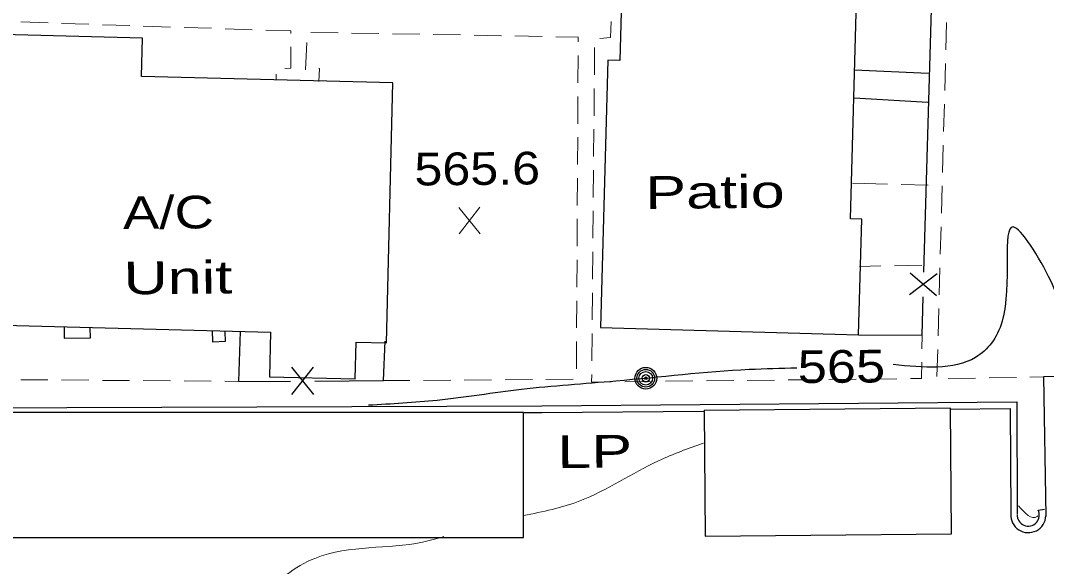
# Model space of a CAD drawing. Extents: x 2361708 to 2370558, y 6977955 to 6991887.
# Drawn here: x 2366045.4 to 2366196.1, y 6987005.8 to 6987086 of the extents above; entities that cross this region are included whole.
import ezdxf
from ezdxf.enums import TextEntityAlignment as Align

# ---------------------------------------------------------------- set-up
doc = ezdxf.new("R2010")
doc.units = 0
doc.header["$LTSCALE"] = 1.9
for name, color, linetype, lineweight in [('11', 7, 'Continuous', 25), ('13', 7, 'Continuous', 13), ('14', 7, 'Continuous', 13), ('17', 7, 'Continuous', 25), ('2', 7, 'Continuous', 25), ('20', 7, 'Continuous', 25), ('23', 7, 'Continuous', 25), ('31', 7, 'Continuous', 13), ('35', 7, 'Continuous', 13)]:
    doc.layers.add(name, color=color, linetype=linetype, lineweight=lineweight)

msp = doc.modelspace()

# ---------------------------------------------------------------- linework, layer by layer
at = {"layer": '11'}
for points in [[(2366135.939, 6987170.918), (2366133.413, 6987080.11), (2366131.692, 6987080.163), (2366130.576, 6987040.891), (2366168.498, 6987039.812), (2366168.976, 6987056.797), (2366167.316, 6987056.842), (2366171.07, 6987192.024), (2366172.87, 6987191.971), (2366173.763, 6987225.311), (2366137.182, 6987226.293), (2366136.753, 6987210.428), (2366134.822, 6987210.48), (2366133.798, 6987170.978)], [(2365971.868, 6987043.1), (2366082.12, 6987040.2), (2366081.953, 6987033.648), (2366094.536, 6987033.318), (2366094.675, 6987038.719), (2366099.136, 6987038.612), (2366100.092, 6987076.843), (2366063.132, 6987077.771), (2366063.278, 6987083.403), (2366042.702, 6987083.917), (2366042.601, 6987079.885), (2365992.386, 6987081.197), (2365992.488, 6987085.159), (2365972.982, 6987085.673)], [(2366145.969, 6987010.236), (2366182.187, 6987010.56), (2366182.021, 6987029.01), (2366145.803, 6987028.685)], [(2366029.615, 6987010.008), (2366119.26, 6987010.002), (2366119.255, 6987028.393), (2366029.61, 6987028.389)]]:
    msp.add_lwpolyline(points, close=True, dxfattribs=at)
at = {"layer": '13'}
for p, q in [((2366045.405, 6987085.762), (2366049.406, 6987085.631)), ((2366051.407, 6987085.56), (2366055.409, 6987085.428)), ((2366057.409, 6987085.357), (2366061.411, 6987085.225)), ((2366063.412, 6987085.154), (2366067.413, 6987085.022)), ((2366069.414, 6987084.961), (2366073.415, 6987084.829)), ((2366075.416, 6987084.758), (2366079.418, 6987084.626)), ((2366088.021, 6987084.228), (2366092.023, 6987084.156)), ((2366181.34, 6987081.676), (2366181.452, 6987085.677)), ((2366087.254, 6987078.751), (2366087.445, 6987082.742)), ((2366094.023, 6987084.125), (2366098.024, 6987084.053)), ((2366100.024, 6987084.023), (2366104.025, 6987083.95)), ((2366106.025, 6987083.92), (2366110.026, 6987083.848)), ((2366112.027, 6987083.807), (2366116.028, 6987083.735)), ((2366118.028, 6987083.704), (2366122.029, 6987083.632)), ((2366129.693, 6987077.994), (2366129.725, 6987081.995)), ((2366127.306, 6987080.822), (2366127.284, 6987076.821)), ((2366181.177, 6987075.674), (2366181.289, 6987079.675)), ((2366082.94, 6987078.089), (2366082.946, 6987077.379)), ((2366129.64, 6987071.993), (2366129.672, 6987075.994)), ((2366127.273, 6987074.821), (2366127.251, 6987070.821)), ((2366181.015, 6987069.673), (2366181.126, 6987073.674)), ((2366129.587, 6987065.993), (2366129.619, 6987069.993)), ((2366127.24, 6987068.821), (2366127.218, 6987064.82)), ((2366180.852, 6987063.671), (2366180.964, 6987067.672)), ((2366129.534, 6987059.992), (2366129.566, 6987063.992)), ((2366127.208, 6987062.82), (2366127.186, 6987058.82)), ((2366180.689, 6987057.669), (2366180.801, 6987061.67)), ((2366129.481, 6987053.991), (2366129.513, 6987057.992)), ((2366127.174, 6987056.82), (2366127.152, 6987052.819)), ((2366180.526, 6987051.667), (2366180.638, 6987055.668)), ((2366129.428, 6987047.99), (2366129.46, 6987051.991)), ((2366127.142, 6987050.819), (2366127.12, 6987046.818)), ((2366180.363, 6987045.665), (2366180.475, 6987049.666)), ((2366129.375, 6987041.99), (2366129.407, 6987045.99)), ((2366127.109, 6987044.818), (2366127.087, 6987040.818)), ((2366180.2, 6987039.663), (2366180.312, 6987043.664)), ((2366129.323, 6987035.989), (2366129.355, 6987039.99)), ((2366177.849, 6987039.761), (2366177.828, 6987037.761)), ((2366127.076, 6987038.817), (2366127.054, 6987034.817)), ((2366180.037, 6987033.661), (2366180.149, 6987037.663)), ((2366049.396, 6987033.178), (2366045.395, 6987033.21)), ((2366055.396, 6987033.135), (2366051.396, 6987033.167)), ((2366061.397, 6987033.082), (2366057.397, 6987033.114)), ((2366067.398, 6987033.039), (2366063.397, 6987033.071)), ((2366073.399, 6987032.986), (2366069.398, 6987033.018)), ((2366077.399, 6987032.954), (2366075.399, 6987032.975)), ((2366102.579, 6987033.094), (2366098.699, 6987033.067)), ((2366108.579, 6987033.141), (2366104.579, 6987033.113)), ((2366114.579, 6987033.188), (2366110.579, 6987033.16)), ((2366120.579, 6987033.236), (2366116.579, 6987033.207)), ((2366126.579, 6987033.283), (2366122.579, 6987033.255)), ((2366138.162, 6987032.953), (2366134.162, 6987032.915)), ((2366144.162, 6987033.02), (2366140.162, 6987032.972)), ((2366150.162, 6987033.087), (2366146.162, 6987033.039)), ((2366156.161, 6987033.154), (2366152.161, 6987033.106)), ((2366162.161, 6987033.211), (2366158.161, 6987033.173)), ((2366168.161, 6987033.278), (2366164.161, 6987033.23)), ((2366174.16, 6987033.346), (2366170.161, 6987033.297)), ((2366185.7, 6987033.435), (2366181.7, 6987033.357)), ((2366191.699, 6987033.542), (2366187.7, 6987033.474)), ((2366195.698, 6987033.62), (2366193.699, 6987033.581))]:
    msp.add_line(p, q, dxfattribs=at)
for points in [[(2366130.472, 6987083.322), (2366132.081, 6987083.467), (2366132.158, 6987085.848)], [(2366081.418, 6987084.565), (2366085.069, 6987084.44), (2366085.073, 6987084.09)], [(2366124.029, 6987083.591), (2366127.32, 6987083.532), (2366127.317, 6987082.822)], [(2366085.072, 6987082.09), (2366085.082, 6987078.96), (2366084.212, 6987078.902)], [(2366089.2, 6987077.029), (2366089.312, 6987078.94), (2366089.222, 6987078.929)], [(2366177.807, 6987035.761), (2366177.78, 6987033.38), (2366176.16, 6987033.365)], [(2366132.162, 6987032.896), (2366129.292, 6987032.859), (2366129.302, 6987033.989)]]:
    msp.add_lwpolyline(points, dxfattribs=at)
at = {"layer": '14'}
for p, q in [((2366172.758, 6987061.954), (2366167.626, 6987062.085)), ((2366178.76, 6987061.801), (2366174.758, 6987061.903)), ((2366171.792, 6987049.914), (2366168.642, 6987049.854)), ((2366177.792, 6987050.031), (2366173.792, 6987049.953))]:
    msp.add_line(p, q, dxfattribs=at)
at = {"layer": '17'}
for p, q in [((2366178.121, 6987049.004), (2366179.85, 6987108.983)), ((2366178.723, 6987078.211), (2366167.938, 6987078.688)), ((2366178.684, 6987073.95), (2366167.848, 6987074.567)), ((2366180.084, 6987048.753), (2366175.993, 6987045.663)), ((2366179.984, 6987045.551), (2366176.082, 6987048.865)), ((2366088.458, 6987031.039), (2366085.23, 6987035.029)), ((2366085.258, 6987031.029), (2366088.43, 6987035.04))]:
    msp.add_line(p, q, dxfattribs=at)
for points in [[(2366168.498, 6987039.812), (2366177.849, 6987039.761), (2366178.015, 6987045.403)], [(2366077.629, 6987040.307), (2366077.399, 6987032.954), (2366085.039, 6987032.997)], [(2366088.639, 6987033.012), (2366098.699, 6987033.067), (2366098.954, 6987038.88)]]:
    msp.add_lwpolyline(points, dxfattribs=at)
at = {"layer": '2'}
msp.add_line((2366194.895, 6987014.062), (2366195.843, 6987014.181), dxfattribs=at)
for points in [[(2366208.105, 6987010.948), (2366206.414, 6987011.061), (2366206.916, 6987033.937), (2366195.698, 6987033.62), (2366196.033, 6987013.173)], [(2365974.12, 6987013.41), (2365974.405, 6987028.664), (2366024.194, 6987029.038), (2366121.985, 6987029.359), (2366191.754, 6987029.932), (2366191.83, 6987013.483)], [(2366119.395, 6987028.394), (2366121.995, 6987028.399), (2366145.734, 6987028.595)], [(2366181.913, 6987028.889), (2366190.803, 6987028.964), (2366190.87, 6987013.474)]]:
    msp.add_lwpolyline(points, dxfattribs=at)
for radius, end in [(2.584, 357.69788), (1.624, 27.12397)]:
    msp.add_arc((2366193.45, 6987013.321), radius, 176.62785, end, dxfattribs=at)
at = {"layer": '20'}
for radius in [1.6, 1.3, 1, 0.539, 0.192]:
    msp.add_circle((2366137.248, 6987033.414), radius, dxfattribs=at)
at = {"layer": '23'}
for p, q in [((2366051.761, 6987041.001), (2366051.787, 6987039.321)), ((2366075.483, 6987038.856), (2366075.429, 6987040.226))]:
    msp.add_line(p, q, dxfattribs=at)
for points in [[(2366051.787, 6987039.321), (2366055.647, 6987039.377), (2366055.623, 6987040.838)], [(2366073.528, 6987040.408), (2366073.593, 6987038.779), (2366075.483, 6987038.856)]]:
    msp.add_lwpolyline(points, dxfattribs=at)
at = {"layer": '31'}
for p, q in [((2366112.915, 6987054.654), (2366109.797, 6987058.504)), ((2366109.834, 6987054.624), (2366112.877, 6987058.533))]:
    msp.add_line(p, q, dxfattribs=at)
at = {"layer": '31', "lineweight": 25}
for points in [[(2366173.555, 6987235.58), (2366177.232, 6987227.574), (2366180.597, 6987211.245), (2366182.521, 6987193.983), (2366185.055, 6987177.887), (2366187.871, 6987157.282), (2366192.809, 6987128.088), (2366196.642, 6987102.603), (2366198.728, 6987086.172), (2366202.37, 6987067.106), (2366202.775, 6987051.879), (2366203.919, 6987040.999), (2366199.342, 6987040.616)], [(2366199.342, 6987040.616), (2366196.754, 6987047.711), (2366191.208, 6987055.659), (2366189.6, 6987041.793), (2366185.711, 6987036.486), (2366173.61, 6987035.43)], [(2366159.444, 6987034.896), (2366152.436, 6987034.689), (2366132.851, 6987032.992), (2366118.972, 6987031.76), (2366106.597, 6987030.172), (2366096.503, 6987029.446)]]:
    msp.add_spline(points, degree=3, dxfattribs=at)
at = {"layer": '35'}
for points in [[(2366380.911, 6986785.251), (2366382.268, 6986813.966), (2366386.258, 6986864.446), (2366388.083, 6986917.526), (2366386.465, 6986969.843), (2366379.229, 6987018.737), (2366369.571, 6987062.657), (2366359.499, 6987118.434), (2366346.515, 6987163.982), (2366332.996, 6987216.326), (2366322.272, 6987255.606), (2366306.828, 6987311.562), (2366294.337, 6987352.575), (2366279.272, 6987408.674), (2366266.557, 6987447.065), (2366255.8, 6987497.105), (2366243.505, 6987538.57), (2366229.92, 6987570.512), (2366220.701, 6987604.986), (2366213.335, 6987636.027), (2366209.054, 6987648.728), (2366203.114, 6987665.562), (2366199.061, 6987672.143), (2366195.396, 6987673.659), (2366195.379, 6987671.298), (2366196.729, 6987663.871), (2366200.485, 6987645.436), (2366204.141, 6987621.679), (2366208.485, 6987591.929), (2366212.795, 6987565.689), (2366219.387, 6987528.72), (2366222.005, 6987515.324), (2366226.955, 6987480.62), (2366230.794, 6987448.235), (2366225.64, 6987440.165), (2366221.723, 6987442.998), (2366219.635, 6987452.238), (2366213.475, 6987477.461), (2366207.959, 6987504.27), (2366198.991, 6987542.896), (2366189.212, 6987578.425), (2366181.456, 6987606.433), (2366172.602, 6987639.37), (2366166.417, 6987654.552), (2366165.282, 6987651.931), (2366167.702, 6987636.203), (2366172.874, 6987607.571), (2366179.239, 6987565.129), (2366184.776, 6987536.041), (2366190.372, 6987503.913), (2366193.368, 6987474.91), (2366195.333, 6987451.277), (2366193.344, 6987436.518), (2366187.295, 6987420.579), (2366179.405, 6987404.803), (2366172.549, 6987391.747), (2366170.736, 6987368.889), (2366168.132, 6987351.434), (2366167.618, 6987340.368), (2366167.813, 6987321.889), (2366167.884, 6987307.079), (2366167.184, 6987302.912)], [(2366145.718, 6987023.904), (2366139.133, 6987021.302), (2366127.549, 6987015.401), (2366119.309, 6987013.242)], [(2366194.863, 6987013.202), (2366194.763, 6987013.12), (2366192.019, 6987014.695)], [(2366107.558, 6987010.16), (2366104.455, 6987009.341), (2366088.617, 6987006.95), (2366081.952, 6987001.096), (2366082.289, 6986994.089), (2366083.821, 6986986.543), (2366084.129, 6986985.766)]]:
    msp.add_spline(points, degree=3, dxfattribs=at)

# ---------------------------------------------------------------- texts
at = {"layer": '14', "width": 1.4}
msp.add_text('Patio', height=4.8, rotation=0.545, dxfattribs=at).set_placement((2366137.201, 6987058.295))
at = {"layer": '20'}
for s, width, p in [('A/C', 1.25, (2366060.435, 6987055.334)), ('Unit', 1.4, (2366060.527, 6987045.735)), ('  LP', 1.4, (2366119.283, 6987020.173))]:
    msp.add_text(s, height=4.8, rotation=0.545, dxfattribs=dict(at, width=width)).set_placement(p)
at = {"layer": '31', "width": 1.15}
msp.add_text('565.6', height=4.8, rotation=0.545, dxfattribs=at).set_placement((2366103.266, 6987061.732))
at = {"layer": '31', "width": 1.2}
msp.add_text(' 565 ', height=4.8, rotation=0.545, dxfattribs=at).set_placement((2366166.019, 6987032.758), align=Align.CENTER)

doc.saveas('drawing.dxf')
